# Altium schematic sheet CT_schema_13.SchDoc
size 390 x 385 mm
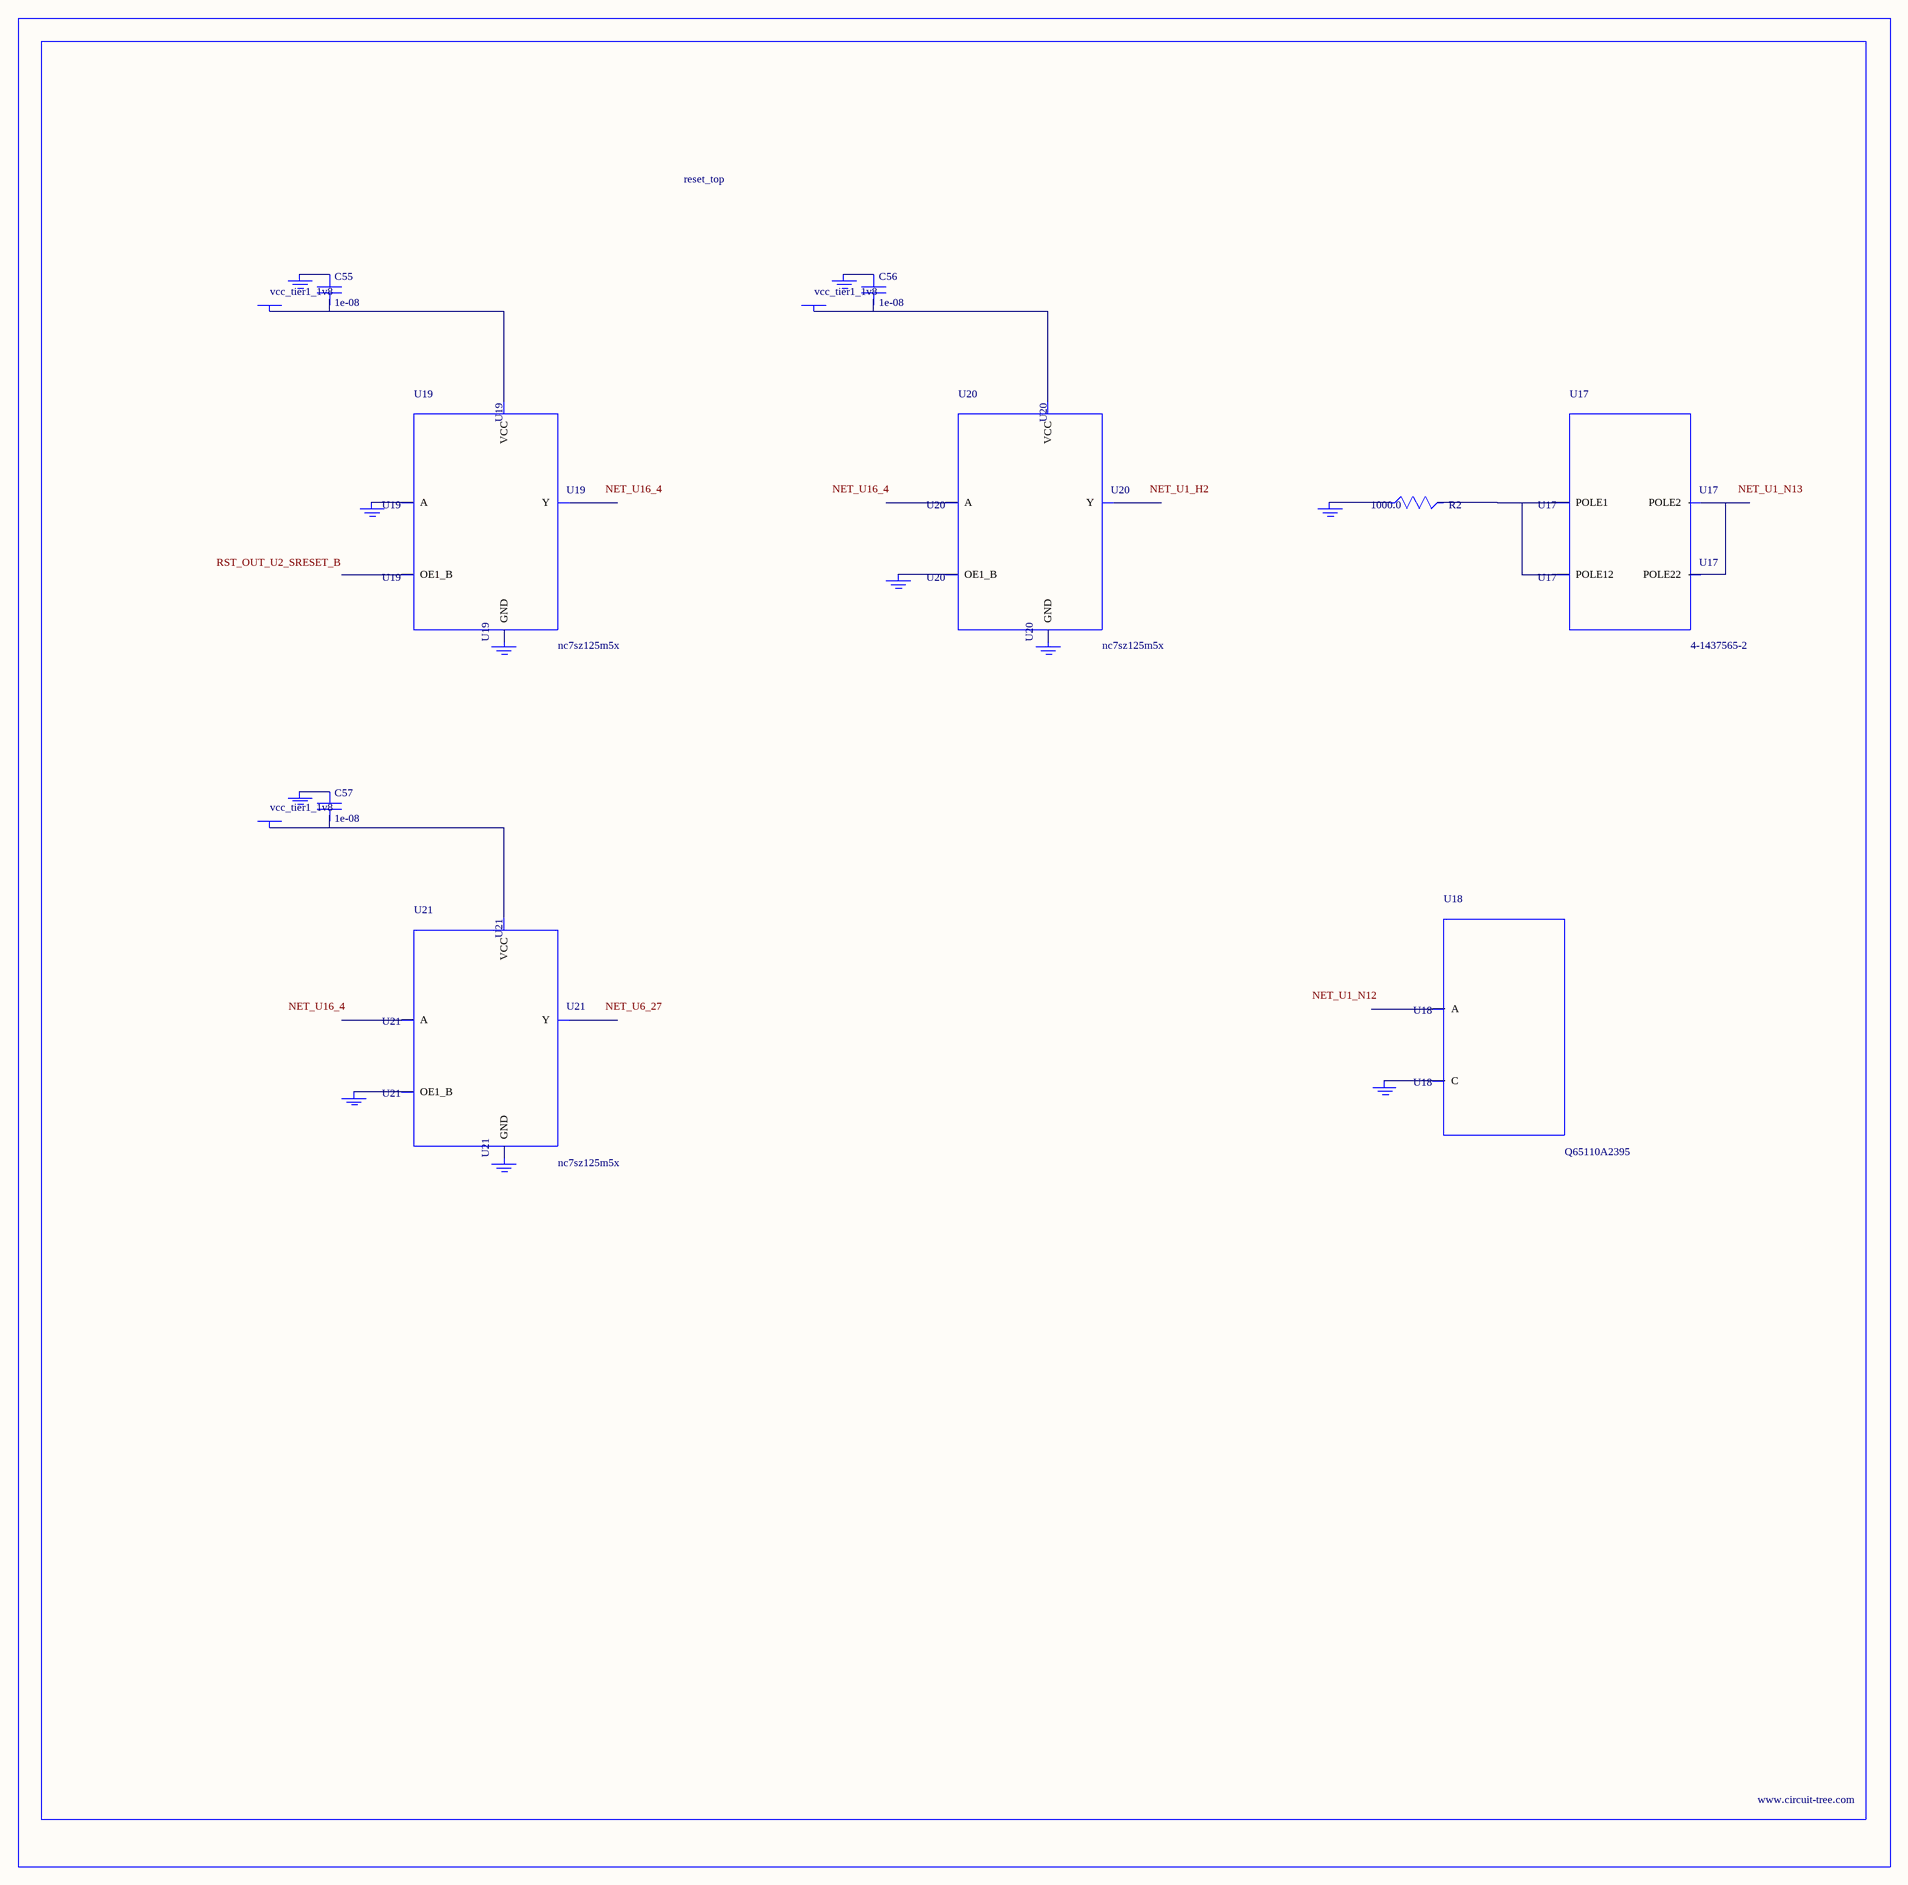
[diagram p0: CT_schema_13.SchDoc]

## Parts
BORDER12  (no value)
C55  1e-08  [C0402]
C56  1e-08  [C0402]
C57  1e-08  [C0402]
GND_INSTANCE_12_0  (no value)
GND_INSTANCE_12_1  (no value)
GND_INSTANCE_12_2  (no value)
GND_INSTANCE_12_3  (no value)
GND_INSTANCE_12_4  (no value)
GND_INSTANCE_12_5  (no value)
GND_INSTANCE_12_6  (no value)
GND_INSTANCE_12_7  (no value)
GND_INSTANCE_12_8  (no value)
GND_INSTANCE_12_9  (no value)
GND_INSTANCE_12_10  (no value)
POWER_INSTANCE_12_0  vcc_tier1_1v8
POWER_INSTANCE_12_1  vcc_tier1_1v8
POWER_INSTANCE_12_2  vcc_tier1_1v8
R2  1000.0  [R0603]
U17  4-1437565-2  [SW_4-1437565-2]
U18  Q65110A2395  [LGM67K-G1J2-24-Z]
U19  nc7sz125m5x  [NC7SZ125M5X]
U20  nc7sz125m5x  [NC7SZ125M5X]
U21  nc7sz125m5x  [NC7SZ125M5X]

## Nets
NetC55_1: C55.1 GND_INSTANCE_12_2.0(GND)
NetC55_2: C55.2 POWER_INSTANCE_12_0.0(PWR) U19.5(VCC)
NetC56_1: C56.1 GND_INSTANCE_12_5.0(GND)
NetC56_2: C56.2 POWER_INSTANCE_12_1.0(PWR) U20.5(VCC)
NetC57_1: C57.1 GND_INSTANCE_12_8.0(GND)
NetC57_2: C57.2 POWER_INSTANCE_12_2.0(PWR) U21.5(VCC)
NetGND_INSTANCE_12_0_0: GND_INSTANCE_12_0.0(GND) R2.1
NetGND_INSTANCE_12_1_0: GND_INSTANCE_12_1.0(GND) U18.C
NetGND_INSTANCE_12_3_0: GND_INSTANCE_12_3.0(GND) U19.2(A)
NetGND_INSTANCE_12_4_0: GND_INSTANCE_12_4.0(GND) U19.3(GND)
NetGND_INSTANCE_12_6_0: GND_INSTANCE_12_6.0(GND) U20.1(OE1_B)
NetGND_INSTANCE_12_7_0: GND_INSTANCE_12_7.0(GND) U20.3(GND)
NetGND_INSTANCE_12_9_0: GND_INSTANCE_12_9.0(GND) U21.1(OE1_B)
NetGND_INSTANCE_12_10_0: GND_INSTANCE_12_10.0(GND) U21.3(GND)
NetR2_2: R2.2 U17.1(POLE1) U17.2(POLE12)
NetU17_3: U17.3(POLE2) U17.4(POLE22)

Not connected (* = marked no-connect by the designer): U18 A; U19 1(OE1_B) 4(Y); U20 2(A) 4(Y); U21 2(A) 4(Y)

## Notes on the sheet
- Labels drawn without touching a wire or pin: NET_U1_H2, NET_U1_N12, NET_U1_N13, NET_U6_27, NET_U16_4, RST_OUT_U2_SRESET_B

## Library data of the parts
BORDER12 = BORDER_PAGE12
C55-C57 = C0402C103K3RAC
GND_INSTANCE_12_0-GND_INSTANCE_12_10 = GND
POWER_INSTANCE_12_0-POWER_INSTANCE_12_2 = PWR
R2 = RC0603JR-071KL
